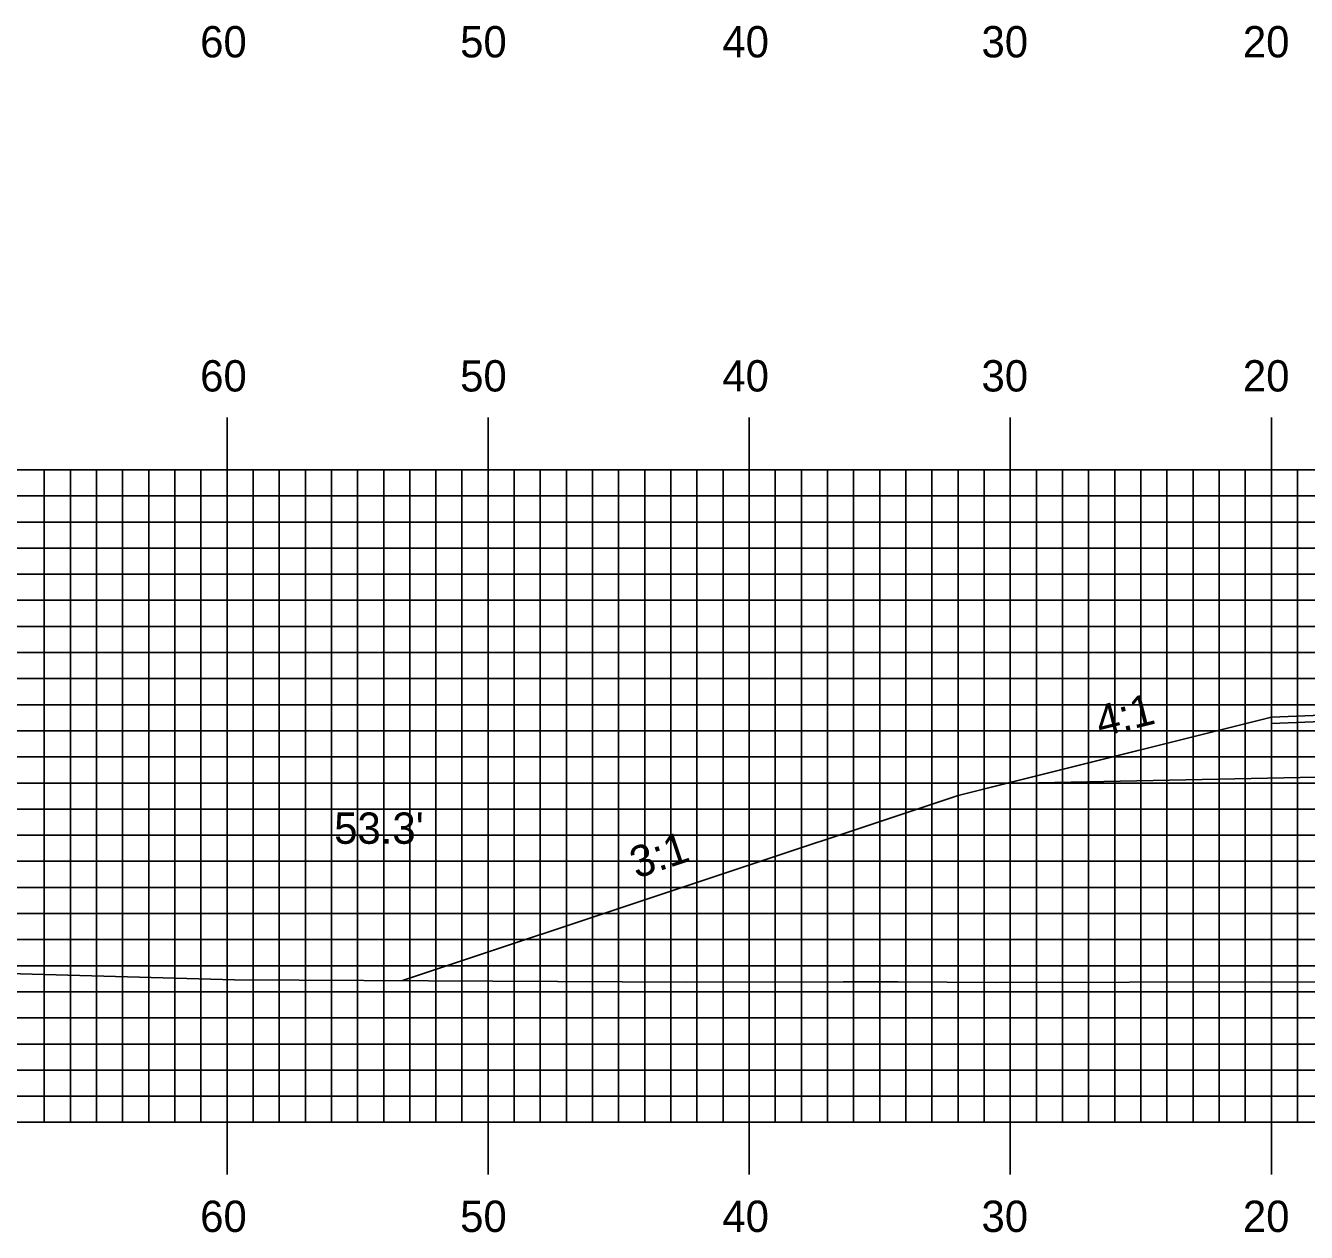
# Model space of a CAD drawing. Extents: x 1819244 to 1819587, y 442591 to 442811.
# Drawn here: x 1819341.95 to 1819391.01, y 442649.45 to 442695.68 of the extents above; entities that cross this region are included whole.
import ezdxf

# ---------------------------------------------------------------- set-up
doc = ezdxf.new("R2010")
doc.units = 0
for name, color, linetype in [('ANNOTATION', 7, 'Continuous'), ('D_Roadway_Centerline', 7, 'Continuous'), ('D_Roadway_Edge_Shoulder', 7, 'Continuous'), ('D_Roadway_SlopeLines', 7, 'Continuous'), ('D_Roadway_SubGrade', 7, 'Continuous'), ('D_Text_Standard', 7, 'Continuous'), ('H_V ANNOTATION', 7, 'Continuous'), ('MAJOR', 7, 'Continuous'), ('MINOR', 7, 'Continuous'), ('S_Roadway_Centerline', 7, 'Continuous')]:
    doc.layers.add(name, color=color, linetype=linetype)

msp = doc.modelspace()

# ---------------------------------------------------------------- linework, layer by layer
at = {"layer": 'D_Roadway_Centerline'}
msp.add_lwpolyline([(1819356.354, 442659.088), (1819377.665, 442666.192), (1819379.491, 442666.648), (1819389.665, 442669.192), (1819397.665, 442669.512), (1819409.665, 442669.752), (1819421.665, 442669.512), (1819429.665, 442669.192), (1819439.839, 442666.648), (1819441.665, 442666.192), (1819462.524, 442659.238)], dxfattribs=at)
at = {"layer": 'D_Roadway_Edge_Shoulder'}
msp.add_lwpolyline([(1819397.665, 442669.512), (1819389.665, 442669.192), (1819389.665, 442668.942), (1819397.665, 442669.262)], close=True, dxfattribs=at)
at = {"layer": 'D_Roadway_SlopeLines'}
msp.add_lwpolyline([(1819389.665, 442669.192), (1819377.665, 442666.192), (1819356.354, 442659.088)], dxfattribs=at)
at = {"layer": 'D_Roadway_SubGrade'}
msp.add_lwpolyline([(1819397.665, 442667.012), (1819379.491, 442666.648), (1819389.665, 442669.192), (1819389.665, 442668.942), (1819397.665, 442669.262), (1819409.665, 442669.502), (1819421.665, 442669.262), (1819429.665, 442668.942), (1819429.665, 442669.192), (1819439.839, 442666.648), (1819421.665, 442667.012), (1819409.665, 442667.252)], close=True, dxfattribs=at)
at = {"layer": 'MAJOR'}
for p, q in [((1819349.665, 442680.669), (1819349.665, 442678.665)), ((1819359.665, 442680.669), (1819359.665, 442678.665)), ((1819369.665, 442680.669), (1819369.665, 442678.665)), ((1819379.665, 442680.669), (1819379.665, 442678.665)), ((1819389.665, 442680.669), (1819389.665, 442678.665)), ((1819269.665, 442678.665), (1819549.665, 442678.665)), ((1819269.665, 442678.665), (1819549.665, 442678.665)), ((1819349.665, 442653.665), (1819349.665, 442678.665)), ((1819359.665, 442653.665), (1819359.665, 442678.665)), ((1819369.665, 442653.665), (1819369.665, 442678.665)), ((1819379.665, 442653.665), (1819379.665, 442678.665)), ((1819389.665, 442653.665), (1819389.665, 442678.665)), ((1819269.665, 442673.665), (1819549.665, 442673.665)), ((1819269.665, 442668.665), (1819549.665, 442668.665)), ((1819269.665, 442663.665), (1819549.665, 442663.665)), ((1819269.665, 442658.665), (1819549.665, 442658.665)), ((1819269.665, 442653.665), (1819549.665, 442653.665)), ((1819269.665, 442653.665), (1819549.665, 442653.665)), ((1819349.665, 442651.661), (1819349.665, 442653.665)), ((1819359.665, 442651.661), (1819359.665, 442653.665)), ((1819369.665, 442651.661), (1819369.665, 442653.665)), ((1819379.665, 442651.661), (1819379.665, 442653.665)), ((1819389.665, 442651.661), (1819389.665, 442653.665))]:
    msp.add_line(p, q, dxfattribs=at)
at = {"layer": 'MINOR'}
for p, q in [((1819342.665, 442653.665), (1819342.665, 442678.665)), ((1819343.665, 442653.665), (1819343.665, 442678.665)), ((1819344.665, 442653.665), (1819344.665, 442678.665)), ((1819345.665, 442653.665), (1819345.665, 442678.665)), ((1819346.665, 442653.665), (1819346.665, 442678.665)), ((1819347.665, 442653.665), (1819347.665, 442678.665)), ((1819348.665, 442653.665), (1819348.665, 442678.665)), ((1819350.665, 442653.665), (1819350.665, 442678.665)), ((1819351.665, 442653.665), (1819351.665, 442678.665)), ((1819352.665, 442653.665), (1819352.665, 442678.665)), ((1819353.665, 442653.665), (1819353.665, 442678.665)), ((1819354.665, 442653.665), (1819354.665, 442678.665)), ((1819355.665, 442653.665), (1819355.665, 442678.665)), ((1819356.665, 442653.665), (1819356.665, 442678.665)), ((1819357.665, 442653.665), (1819357.665, 442678.665)), ((1819358.665, 442653.665), (1819358.665, 442678.665)), ((1819360.665, 442653.665), (1819360.665, 442678.665)), ((1819361.665, 442653.665), (1819361.665, 442678.665)), ((1819362.665, 442653.665), (1819362.665, 442678.665)), ((1819363.665, 442653.665), (1819363.665, 442678.665)), ((1819364.665, 442653.665), (1819364.665, 442678.665)), ((1819365.665, 442653.665), (1819365.665, 442678.665)), ((1819366.665, 442653.665), (1819366.665, 442678.665)), ((1819367.665, 442653.665), (1819367.665, 442678.665)), ((1819368.665, 442653.665), (1819368.665, 442678.665)), ((1819370.665, 442653.665), (1819370.665, 442678.665)), ((1819371.665, 442653.665), (1819371.665, 442678.665)), ((1819372.665, 442653.665), (1819372.665, 442678.665)), ((1819373.665, 442653.665), (1819373.665, 442678.665)), ((1819374.665, 442653.665), (1819374.665, 442678.665)), ((1819375.665, 442653.665), (1819375.665, 442678.665)), ((1819376.665, 442653.665), (1819376.665, 442678.665)), ((1819377.665, 442653.665), (1819377.665, 442678.665)), ((1819378.665, 442653.665), (1819378.665, 442678.665)), ((1819380.665, 442653.665), (1819380.665, 442678.665)), ((1819381.665, 442653.665), (1819381.665, 442678.665)), ((1819382.665, 442653.665), (1819382.665, 442678.665)), ((1819383.665, 442653.665), (1819383.665, 442678.665)), ((1819384.665, 442653.665), (1819384.665, 442678.665)), ((1819385.665, 442653.665), (1819385.665, 442678.665)), ((1819386.665, 442653.665), (1819386.665, 442678.665)), ((1819387.665, 442653.665), (1819387.665, 442678.665)), ((1819388.665, 442653.665), (1819388.665, 442678.665)), ((1819390.665, 442653.665), (1819390.665, 442678.665)), ((1819269.665, 442677.665), (1819549.665, 442677.665)), ((1819269.665, 442676.665), (1819549.665, 442676.665)), ((1819269.665, 442675.665), (1819549.665, 442675.665)), ((1819269.665, 442674.665), (1819549.665, 442674.665)), ((1819269.665, 442672.665), (1819549.665, 442672.665)), ((1819269.665, 442671.665), (1819549.665, 442671.665)), ((1819269.665, 442670.665), (1819549.665, 442670.665)), ((1819269.665, 442669.665), (1819549.665, 442669.665)), ((1819269.665, 442667.665), (1819549.665, 442667.665)), ((1819269.665, 442666.665), (1819549.665, 442666.665)), ((1819269.665, 442665.665), (1819549.665, 442665.665)), ((1819269.665, 442664.665), (1819549.665, 442664.665)), ((1819269.665, 442662.665), (1819549.665, 442662.665)), ((1819269.665, 442661.665), (1819549.665, 442661.665)), ((1819269.665, 442660.665), (1819549.665, 442660.665)), ((1819269.665, 442659.665), (1819549.665, 442659.665)), ((1819269.665, 442657.665), (1819549.665, 442657.665)), ((1819269.665, 442656.665), (1819549.665, 442656.665)), ((1819269.665, 442655.665), (1819549.665, 442655.665)), ((1819269.665, 442654.665), (1819549.665, 442654.665))]:
    msp.add_line(p, q, dxfattribs=at)
at = {"layer": 'S_Roadway_Centerline'}
msp.add_lwpolyline([(1819269.665, 442661.815), (1819272.843, 442661.651), (1819288.177, 442660.543), (1819298.828, 442660.207), (1819305.798, 442659.821), (1819309.315, 442659.838), (1819324.015, 442659.645), (1819335.7, 442659.474), (1819338.556, 442659.445), (1819349.95, 442659.119), (1819367.277, 442659.035), (1819373.268, 442659.053), (1819375.373, 442659.045), (1819379.124, 442659.023), (1819389.341, 442659.046), (1819399.588, 442659.041), (1819406.619, 442659.2), (1819413.605, 442659.425), (1819427.617, 442659.947), (1819441.069, 442659.597), (1819445.916, 442659.512), (1819453.663, 442659.344), (1819475.455, 442659.085)], dxfattribs=at)

# ---------------------------------------------------------------- texts
at = {"layer": 'ANNOTATION'}
for s, rotation, p in [('4:1', 14.0362, (1819383.113, 442668.415)), ('3:1', 18.4348, (1819365.348, 442662.994))]:
    msp.add_text(s, height=1.2, rotation=rotation, dxfattribs=at).set_placement(p)
at = {"layer": 'D_Text_Standard'}
msp.add_text("53.3'", height=1.2, dxfattribs=at).set_placement((1819353.769, 442664.336))
at = {"layer": 'H_V ANNOTATION'}
for s, p in [('60', (1819348.637, 442694.465)), ('50', (1819358.594, 442694.465)), ('40', (1819368.637, 442694.465)), ('30', (1819378.562, 442694.465)), ('20', (1819388.573, 442694.465)), ('60', (1819348.637, 442681.665)), ('50', (1819358.594, 442681.665)), ('40', (1819368.637, 442681.665)), ('30', (1819378.562, 442681.665)), ('20', (1819388.573, 442681.665)), ('60', (1819348.637, 442649.465)), ('50', (1819358.594, 442649.465)), ('40', (1819368.637, 442649.465)), ('30', (1819378.562, 442649.465)), ('20', (1819388.573, 442649.465))]:
    msp.add_text(s, height=1.2, dxfattribs=at).set_placement(p)

doc.saveas('drawing.dxf')
